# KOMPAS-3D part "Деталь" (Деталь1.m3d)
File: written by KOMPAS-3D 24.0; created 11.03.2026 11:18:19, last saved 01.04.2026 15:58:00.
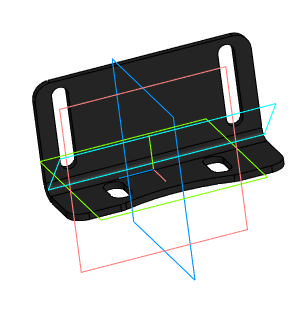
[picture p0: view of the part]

Document properties: Автор: R2D2; Полное имя файла: E:\Работа\Зайцев\Аксессуары для пневмоприводов\Блок концевых выключателей DN.ru\APL-310N Блок концевых выключателей DN.ru\исходные материалы\Деталь1.m3d

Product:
- Part/product: Деталь
    Масса: 0.047126

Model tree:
1. Эскиз:1
2. Листовое тело:1
     Расстояние 1 = 65; Радиус сгиба = 3; Коэффициент = 0.4; Величина сгиба = 10
3. Эскиз:2  (with: Грань.Листовое тело:1, Ребро.Листовое тело:1)
4. Вырез в листовом теле:1
     Глубина выреза = 10
5. Средняя плоскость:1  (with: Грань.Листовое тело:1)
6. Эскиз:3  (with: Грань.Листовое тело:1)
7. Элемент выдавливания:1
     Расстояние 2 = 10
8. Зеркальный массив:2
9. Экземпляр ( 1 )
10. Экземпляр ( 2 )  (with: Элемент выдавливания:1)
11. Скругление:1  (with: Ребро.Листовое тело:1, Ребро.Вырез в листовом теле:1)
     Радиус = 5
